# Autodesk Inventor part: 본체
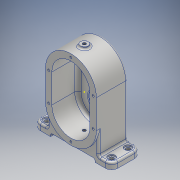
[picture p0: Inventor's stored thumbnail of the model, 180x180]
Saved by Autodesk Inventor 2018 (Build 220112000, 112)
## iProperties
Created: 2021-05
Part Number: 본체
Material: 알루미늄 6061
Document SubType Name: Modeling
Designer: Admin
Density: 2.7 g/cm^3
Appearance: 알루미늄 - 평지
Mass: 752.781 g
Surface Area: 586.95 cm^2
Volume: 278.808 cm^3
Author: Admin
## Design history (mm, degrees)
sketch "스케치1"
  geometry: L1 (56, 0)-(-56, 0) reference; L2 (0, -87.5)-(0, 87.5) reference; L3 (0, 22.5)-(0, -22.5); L4 (40, 22.5)-(40, -22.5); L5 (-40, -22.5)-(-40, 22.5); A1 r 40 centre (0, 22.5) between (40, 22.5) and (-40, 22.5); A2 r 40 centre (0, -22.5) between (-40, -22.5) and (40, -22.5); 2 further points
  constraints: 8 end point, 4 point on circle, 4 tangent, 2 centre point, 2 point on line, 1 midpoint, 1 parallel, 1 symmetric about line
  dimensions: "d0" = 80 distance between parallel lines of L5 L4; "d1" = 45 distance of L3.end L3.start
extrude "돌출1" new body sketch "스케치1" distance "d2" = 28; taper "d4" = 0 deg; dims "d3" = 21, "d5" = 0
sketch "스케치2"
  geometry: 1 further point
node "작업 평면1"
sketch "스케치3"
  geometry: L1 (40, 28)-(40, -21) reference; L2 (-40, 28)-(40, 28) reference; L3 (-40, -21)-(-40, 28) reference; L4 (40, -21)-(-40, -21) reference; L5 (-56, 0)-(56, 0) reference; L6 (0, -30.8)-(0, 37.8) reference; L7 (-61, -18)-(61, -18); L8 (61, -18)-(61, 28); L9 (61, 28)-(-61, 28); L10 (-61, 28)-(-61, -18); L11 (-61, -18)-(61, 28); L12 (61, -18)-(-61, 28); 2 further points
  constraints: 12 end point, 2 midpoint, 2 parallel, 1 horizontal, 1 perpendicular, 1 point on line
  dimensions: "d7" = 122 distance between parallel lines of L8 L10; "d8" = 3 distance between parallel lines of L4 L7; "d9" = 46 distance between parallel lines of L7 L9
extrude "돌출2" join sketch "스케치3" distance "d10" = 10; taper "d11" = 0 deg
sketch "스케치4"
  geometry: L1 (40, 28)-(40, -21) reference; L2 (-40, 28)-(40, 28) reference; L3 (-40, -21)-(-40, 28) reference; L4 (40, -21)-(-40, -21) reference; L5 (-61, -18)-(61, -18) reference; L6 (-40, 28)-(40, 28); L7 (40, 28)-(40, -18); L8 (40, -18)-(-40, -18); L9 (-40, -18)-(-40, 28); 1 further point
  constraints: 8 end point, 2 parallel, 2 point on line, 1 horizontal, 1 perpendicular
extrude "돌출3" join sketch "스케치4" distance "d12" = 50; taper "d13" = 0 deg
sketch "스케치5"
  geometry: L1 (61, 59.5)-(40, 59.5) reference; L2 (61, 69.5)-(61, 59.5) reference; L3 (61, 69.5)-(-61, 69.5) reference; L4 (-61, 69.5)-(-61, 59.5) reference; L5 (-40, 59.5)-(-61, 59.5) reference; L6 (-40, 59.5)-(-40, -22.5) reference; L7 (40, -22.5)-(40, 59.5) reference; L8 (-85.4, 0)-(85.4, 0) reference; L9 (0, 95.9)-(0, -88.9) reference; L10 (0, -22.5)-(0, 22.5); L11 (26, -22.5)-(26, 22.5); L12 (-26, 22.5)-(-26, -22.5); A1 r 40 centre (0, -22.5) between (-40, -22.5) and (40, -22.5) reference; A2 r 26 centre (0, -22.5) between (-26, -22.5) and (26, -22.5); A3 r 26 centre (0, 22.5) between (26, 22.5) and (-26, 22.5); 2 further points
  constraints: 8 end point, 4 point on circle, 4 tangent, 2 centre point, 1 midpoint, 1 parallel, 1 point on line, 1 symmetric about line
  dimensions: "d14" = 52 distance between parallel lines of L12 L11
extrude "돌출4" join sketch "스케치5" distance "d15" = 11; taper "d16" = 0 deg
sketch "스케치6"
  geometry: L1 (-85.4, 0)-(85.4, 0) reference; L2 (0, 95.9)-(0, -88.9) reference; L3 (26, -22.5)-(26, 22.5) reference; L4 (-26, 22.5)-(-26, -22.5) reference; L5 (26, 7.5)-(22, 7.5); L6 (22, 7.5)-(-26, 7.5); L7 (26, 22.5)-(26, -22.5) reference; L8 (26, -22.5)-(26, 7.5); L9 (-26, -22.5)-(-26, 7.5); A1 r 26 centre (0, 22.5) between (26, 22.5) and (-26, 22.5) reference; A2 r 26 centre (0, -22.5) between (-26, -22.5) and (26, -22.5) reference; A3 r 26 centre (0, -22.5) between (-26, -22.5) and (26, -22.5); 1 further point
  constraints: 8 end point, 3 point on line, 2 collinear, 2 point on circle, 1 centre point, 1 coincident, 1 perpendicular
  dimensions: "d17" = 30 distance from line of L6 A2.centre
extrude "돌출5" cut sketch "스케치6" distance "d18" = 3; taper "d19" = 0 deg
node "작업 평면2"
sketch "스케치8"
  geometry: L1 (0, -33)-(0, 51) reference; L2 (-40, -21)-(40, -21) reference; C1 r 6 at (0, 0); 1 further point
  constraints: 1 centre point, 1 point on line
  dimensions: "d21" = 21 distance from line of L2 C1.centre; "d22" = 12 diameter of C1
extrude "돌출6" join sketch "스케치8" distance "d23" = 10; taper "d24" = 0 deg
sketch "스케치9"
  geometry: L1 (-40, 22.5)-(-40, -22.5) reference; L2 (40, -22.5)-(40, 22.5) reference; L3 (0, -96.5)-(0, 92.5) reference; L4 (-85.4, 0)-(85.4, 0) reference; L5 (0, 22.5)-(0, -22.5); L6 (-30, 22.5)-(-30, -22.5); L7 (30, -22.5)-(30, 22.5); A1 r 40 centre (0, -22.5) between (-40, -22.5) and (40, -22.5) reference; A2 r 40 centre (0, 22.5) between (40, 22.5) and (-40, 22.5) reference; A3 r 30 centre (0, 22.5) between (30, 22.5) and (-30, 22.5); A4 r 30 centre (0, -22.5) between (-30, -22.5) and (30, -22.5); 2 further points
  constraints: 8 end point, 4 point on circle, 4 tangent, 2 centre point, 1 collinear, 1 midpoint, 1 parallel
  dimensions: "d25" = 60 distance between parallel lines of L7 L6
extrude "돌출7" cut sketch "스케치9" distance "d26" = 41; taper "d27" = 0 deg
sketch "스케치10"
  geometry: L1 (-30, -22.5)-(-30, 22.5) reference; L2 (30, 22.5)-(30, -22.5) reference; C1 r 14 at (0, 22.5); C2 r 14 at (0, -22.5); A1 r 30 centre (0, -22.5) between (-30, -22.5) and (30, -22.5) reference; A2 r 30 centre (0, 22.5) between (30, 22.5) and (-30, 22.5) reference; 1 further point
  constraints: 2 centre point, 2 coincident
  dimensions: "d28" = 28 diameter of C1; "d29" = 28 diameter of C2 (= d28)
extrude "돌출8" cut sketch "스케치10" distance "d30" = 8; taper "d31" = 0 deg
sketch "스케치11"
  geometry: L1 (26, 7.5)-(26, -22.5) reference; L2 (-26, 7.5)-(26, 7.5) reference; L3 (-26, -22.5)-(-26, 7.5) reference; C1 r 14 at (0, -22.5); A1 r 26 centre (0, -22.5) between (-26, -22.5) and (26, -22.5) reference; 1 further point
  constraints: 1 centre point, 1 coincident
  dimensions: "d32" = 28 diameter of C1
extrude "돌출9" cut sketch "스케치11" distance "d33" = 4; taper "d34" = 0 deg
sketch "스케치12"
  geometry: C1 r 14 at (0, 0) reference; C2 r 11 at (0, 0); 1 further point
  constraints: 1 centre point, 1 coincident
  dimensions: "d35" = 22 diameter of C2
extrude "돌출10" cut sketch "스케치12" extent not by distance; stored distance "d36" = 4; taper "d37" = 0 deg
sketch "스케치13"
  geometry: L1 (-30, 0)-(-30, 45) reference; L2 (30, 45)-(30, 0) reference; C1 r 14 at (0, 45) reference; C2 r 14 at (0, 0) reference; C3 r 10 at (0, 0); A1 r 30 centre (0, 0) between (-30, 0) and (30, 0) reference; A2 r 30 centre (0, 45) between (30, 45) and (-30, 45) reference; 1 further point
  constraints: 1 centre point, 1 coincident
  dimensions: "d38" = 20 diameter of C3
extrude "돌출11" cut sketch "스케치13" distance "d39" = 4; taper "d40" = 0 deg
sketch "스케치14"
  geometry: L1 (-85.4, 0)-(85.4, 0) reference; L2 (0, -96.5)-(0, 92.5) reference; L3 (-30, -22.5)-(-30, 22.5) reference; L4 (30, 22.5)-(30, -22.5) reference; L5 (-40, 22.5)-(-40, -22.5) reference; L6 (40, -22.5)-(40, 22.5) reference; A1 r 30 centre (0, -22.5) between (-30, -22.5) and (30, -22.5) reference; A2 r 30 centre (0, 22.5) between (30, 22.5) and (-30, 22.5) reference; A3 r 40 centre (0, -22.5) between (-40, -22.5) and (40, -22.5) reference; A4 r 40 centre (0, 22.5) between (40, 22.5) and (-40, 22.5) reference; 4 further points
  constraints: 1 point on line, 1 symmetric about line
  dimensions: "d41" = 70 distance of point (35, 22.5) point (-35, 22.5); "d42" = 22.5 distance from line of L1 point (35, 22.5); "d43" = 35 horizontal distance of point (35, 22.5) point (0, 57.5)
hole "구멍1" sketch "스케치14" at (0, 57.5), (-35, 22.5), (35, 22.5) diameter "d44" = 3.242; stored, may be unused: countersink angle "d48" = 90 deg, drill point angle "d50" = 118 deg; dims "d45" = 8, "d46" = 4, "d47" = 2, "d49" = 10
sketch "스케치15"
  geometry: L1 (-85.4, 0)-(85.4, 0) reference; L2 (0, 96.5)-(0, -92.5) reference; L3 (26, 7.5)-(26, -22.5) reference; L4 (-26, 7.5)-(26, 7.5) reference; L5 (-26, -22.5)-(-26, 7.5) reference; C1 r 14 at (0, -22.5) reference; A1 r 26 centre (0, -22.5) between (-26, -22.5) and (26, -22.5) reference; 2 further points
  constraints: 1 point on line
  dimensions: "d51" = 20 distance of C1.centre point (0, -42.5)
hole "구멍2" sketch "스케치15" at (0, -42.5) diameter "d52" = 3.242; stored, may be unused: countersink angle "d56" = 90 deg, drill point angle "d58" = 118 deg; dims "d53" = 8, "d54" = 4, "d55" = 2, "d57" = 10
fillet "모깎기1" dims "d62" = 10
sketch "스케치16"
  geometry: L1 (51, 28)-(-51, 28) reference; L2 (61, -8)-(61, 18) reference; L3 (-51, -18)-(51, -18) reference; L4 (-61, 18)-(-61, -8) reference; A1 r 10 centre (-51, 18) between (-51, 28) and (-61, 18) reference; A2 r 10 centre (51, 18) between (61, 18) and (51, 28) reference; A3 r 10 centre (51, -8) between (51, -18) and (61, -8) reference; A4 r 10 centre (-51, -8) between (-61, -8) and (-51, -18) reference; 5 further points
  constraints: 4 coincident
hole "구멍3" sketch "스케치16" at (51, 18), (51, -8), (-51, -8), (-51, 18) diameter "d63" = 6.6; stored, may be unused: countersink angle "d67" = 90 deg, drill point angle "d69" = 118 deg; dims "d64" = 6, "d65" = 11, "d66" = 2, "d68" = 8
sketch "스케치17"
  geometry: 2 further points
  constraints: 1 coincident
hole "구멍4" sketch "스케치17" at (0, 0) diameter "d70" = 4.917; stored, may be unused: countersink angle "d74" = 90 deg, drill point angle "d76" = 118 deg; dims "d71" = 17, "d72" = 11, "d73" = 2, "d75" = 17.1
sketch "스케치18"
  geometry: L1 (-35, -52)-(35, -52); L2 (35, -52)-(35, -42); L3 (35, -42)-(-35, -42); L4 (-35, -42)-(-35, -52); L5 (51, -47)-(-51, -47) reference; L6 (-35, -52)-(35, -42); L7 (35, -52)-(-35, -42); 2 further points
  constraints: 12 end point, 3 midpoint, 2 parallel, 1 horizontal, 1 perpendicular
  dimensions: "d77" = 10 distance between parallel lines of L3 L1; "d78" = 70 distance between parallel lines of L2 L4
extrude "돌출12" cut sketch "스케치18" extent not by distance; stored distance "d79" = 10; taper "d80" = 0 deg
sketch "스케치19"
  geometry: C1 r 2.458 at (35, 18) reference; 2 further points
  constraints: 1 coincident
hole "구멍5" sketch "스케치19" at (35, 18) diameter "d81" = 4.917; stored, may be unused: countersink angle "d85" = 90 deg, drill point angle "d87" = 118 deg; dims "d82" = 17, "d83" = 12, "d84" = 1, "d86" = 17
fillet "모깎기2" dims "d88" = 3
chamfer "모따기1" distance "d89" = 1; stored, may be unused: second distance "d90" = 2, angle "d91" = 45 deg
fillet "모깎기3" dims "d92" = 0.3
node "작업 평면3"
sketch "스케치20"
  geometry: L1 (51, 69.5)-(35, 69.5) reference; L2 (40, -22.5)-(40, 56.5) reference; 2 further points
  constraints: 1 other
  dimensions: "d94" = 12 distance from line of L1 point (0, 57.5); "d95" = 40 distance from line of L2 point (0, 57.5)
feature "엠보싱1" sketch "스케치20" dims "d7" = 122, "d8" = 3, "d9" = 46, "d96" = 0.5, "d97" = 0
fillet "모깎기4" dims "d98" = 5
node "솔리드1"
mirror "미러1"
pattern_circular "원형 패턴1" dims angle "d60" = 360 deg
node "투영된 루프1"
node "투영된 루프2"
node "투영된 루프3"
node "투영된 루프4"
node "투영된 루프5"
node "투영된 루프6"
node "투영된 루프7"
node "투영된 루프8"
node "투영된 루프9"
node "투영된 루프10"
node "투영된 루프11"
node "투영된 루프12"
other parameters: "d6" = -69.5, "d20" = 135, "d93" = 32.75
